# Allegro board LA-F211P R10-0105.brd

Outline 172.74 x 113.1 mm; copper layers: TOP, GND1, IN1, GND2, IN2, VCC, GND3, IN3, GND4, BOTTOM. Coordinates in mm from the lower left corner of the outline.
Outline path: 0,71.25 0,57.53 arc(0.09,57.24) 0.33,57.06 arc(0.57,56.88) 0.66,56.59 0.66,54.99 arc(0.7,54.8) 0.81,54.63 2.16,53.28 arc(2.27,53.11) 2.31,52.92 2.31,49.34 arc(2.27,49.15) 2.16,48.98 1.76,48.58 arc(1.65,48.41) 1.61,48.22 1.61,47.2 arc(1.5,46.88) 1.2,46.71 arc(0.91,46.54) 0.8,46.22 0.8,28.6 arc(0.95,28.24) 1.31,28.1 arc(1.66,27.96) 1.81,27.6 1.81,21.51 arc(1.66,21.16) 1.31,21.01 1.16,21.01 arc(0.81,20.86) 0.66,20.51 0.66,2.97 arc(0.81,2.62) 1.16,2.47 1.31,2.47 arc(1.66,2.32) 1.81,1.97 1.81,1 arc(2.1,0.29) 2.81,0 97.06,0 97.06,0.32 arc(98.21,1.47) 99.36,0.32 99.36,0 108.01,0 arc(108.72,0.29) 109.01,1 109.01,2.2 arc(109.16,2.55) 109.51,2.7 115.51,2.7 arc(115.81,2.6) 115.99,2.35 arc(116.17,2.1) 116.46,2 133.66,2 arc(134.01,1.85) 134.16,1.5 134.16,0.5 arc(134.31,0.15) 134.66,0 154.16,0 arc(154.51,0.15) 154.66,0.5 arc(154.81,0.85) 155.16,1 160.16,1 arc(160.51,0.85) 160.66,0.5 arc(160.81,0.15) 161.16,0 170.74,0 arc(172.15,0.59) 172.74,2 172.74,7 arc(172.52,7.92) 171.9,8.63 arc(161.15,19.71) 155.07,33.9 arc(154.79,34.35) 154.29,34.52 153.55,34.52 arc(153.04,34.7) 152.76,35.17 arc(152.24,38.83) 152.03,42.51 arc(152.26,43.08) 152.83,43.32 153.22,43.32 arc(153.79,43.55) 154.02,44.12 154.02,93.99 arc(153.89,94.49) 153.52,94.85 arc(152.79,95.59) 152.52,96.59 152.52,108.3 arc(152.67,108.65) 153.02,108.8 153.42,108.8 arc(153.77,108.95) 153.92,109.3 153.92,112.1 arc(153.63,112.81) 152.92,113.1 149.94,113.1 arc(149.66,113.06) 149.41,112.95 arc(148.9,112.73) 148.36,112.65 76.23,112.65 arc(75.52,112.36) 75.23,111.65 75.23,109.65 arc(74.94,108.94) 74.23,108.65 29.23,108.65 arc(27.82,108.06) 27.23,106.65 27.23,105.73 arc(26.64,104.32) 25.23,103.73 17.61,103.73 arc(16.2,104.32) 15.61,105.73 15.61,108.65 arc(15.02,110.06) 13.61,110.65 9.07,110.65 arc(8.49,110.71) 7.92,110.88 arc(7.55,110.99) 7.16,111.03 2.66,111.03 arc(1.25,110.44) 0.66,109.03 0.66,108.72 arc(0.81,108.37) 1.16,108.22 3.56,108.22 arc(4.46,107.32) 3.56,106.42 2.35,106.42 arc(1.64,106.13) 1.35,105.42 1.35,103.69 arc(1.5,103.34) 1.85,103.19 5.25,103.19 arc(5.75,103.69) 6.25,103.19 6.25,94.24 arc(5.75,93.74) 5.25,94.24 1.16,94.24 arc(0.81,94.09) 0.66,93.74 0.66,93.08 arc(0.77,92.77) 1.04,92.59 arc(1.6,92.24) 1.81,91.62 1.81,89.62 arc(1.6,89) 1.04,88.65 arc(0.77,88.47) 0.66,88.16 0.66,87.49 arc(0.81,87.14) 1.16,86.99 5.25,86.99 arc(5.75,87.49) 6.25,86.99 6.25,78.04 arc(5.75,77.54) 5.25,78.04 1.85,78.04 arc(1.5,77.89) 1.35,77.54 1.35,75.91 arc(1.5,75.56) 1.85,75.41 3.56,75.41 arc(4.2,75.15) 4.46,74.51 4.46,74.01 arc(4.2,73.37) 3.56,73.11 1.16,73.11 arc(0.81,72.96) 0.66,72.61 0.66,72.19 arc(0.57,71.9) 0.33,71.72 arc(0.09,71.54) 0,71.25

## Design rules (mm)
constraint set DEFAULT: min track width 0.127
net group ACC2_I2C_SCK: nets ACC2_I2C_SCK ACC2_I2C_SDA
net group ACC2_I2C_SCK1: nets ACC2_I2C_SCK1 ACC2_I2C_SDA1
net group CLK_PCIE_0: nets CLK_PCIE_N0 CLK_PCIE_P0
net group CLK_PEG_7: nets CLK_PEG_N7 CLK_PEG_P7
net group CPU_DP1_0: nets CPU_DP1_N0 CPU_DP1_P0
net group CPU_DP1_1: nets CPU_DP1_N1 CPU_DP1_P1
net group CPU_DP1_2: nets CPU_DP1_N2 CPU_DP1_P2
net group CPU_DP1_3: nets CPU_DP1_N3 CPU_DP1_P3
net group CPU_DP1_AUX: nets CPU_DP1_AUXN CPU_DP1_AUXP
net group CPU_DP2_0: nets CPU_DP2_N0 CPU_DP2_P0
net group CPU_DP2_0_C: nets CPU_DP2_N0_C CPU_DP2_P0_C
net group CPU_DP2_1: nets CPU_DP2_N1 CPU_DP2_P1
net group CPU_DP2_1_C: nets CPU_DP2_N1_C CPU_DP2_P1_C
net group CPU_DP2_2: nets CPU_DP2_N2 CPU_DP2_P2
net group CPU_DP2_2_C: nets CPU_DP2_N2_C CPU_DP2_P2_C
net group CPU_DP2_3: nets CPU_DP2_N3 CPU_DP2_P3
net group CPU_DP2_3_C: nets CPU_DP2_N3_C CPU_DP2_P3_C
net group CPU_DP2_AUX: nets CPU_DP2_AUXN CPU_DP2_AUXP
net group CPU_DP2_AUX_C: nets CPU_DP2_AUXN_C CPU_DP2_AUXP_C
net group CPU_DP3_AUX: nets CPU_DP3_AUXN CPU_DP3_AUXP
net group CPU_DP3_AUX_C: nets CPU_DP3_AUXN_C CPU_DP3_AUXP_C
net group CRITICAL: nets CLINK_CLK SUSCLK
net group DDR-ALERT: nets DDR_A_ALERT# DDR_B_ALERT#
net group GPU_I2C_SCL_R: nets GPU_I2C_SCL_R GPU_I2C_SDA_R
net group HDA_CLK: nets HDA_BIT_CLK HDA_BIT_CLK_R
net group I2C0_SCK_TS: nets I2C0_SCK_TS I2C0_SDA_TS
net group ISH_I2C0_SCK: nets ISH_I2C0_SCK ISH_I2C0_SDA
net group PBAT_CHARGER_SMBCLK: nets PBAT_CHARGER_SMBCLK PBAT_CHARGER_SMBDAT
net group PCH_CPU_BCLK: nets PCH_CPU_BCLK_N PCH_CPU_BCLK_P
net group PCH_CPU_PCIBCLK: nets PCH_CPU_PCIBCLK_N PCH_CPU_PCIBCLK_P
net group PCIE_PRX_C_DTX_5: nets PCIE_PRX_C_DTX_N5 PCIE_PRX_C_DTX_P5
net group PCIE_PRX_C_TTX_9: nets PCIE_PRX_C_TTX_N9 PCIE_PRX_C_TTX_P9
net group PCIE_PRX_C_TTX_10: nets PCIE_PRX_C_TTX_N10 PCIE_PRX_C_TTX_P10
net group PCIE_PRX_C_TTX_11: nets PCIE_PRX_C_TTX_N11 PCIE_PRX_C_TTX_P11
net group PCIE_PRX_C_TTX_12: nets PCIE_PRX_C_TTX_N12 PCIE_PRX_C_TTX_P12
net group PCIE_PRX_DTX_1: nets PCIE_PRX_DTX_N1 PCIE_PRX_DTX_P1
net group PCIE_PRX_DTX_5: nets PCIE_PRX_DTX_N5 PCIE_PRX_DTX_P5
net group PCIE_PRX_DTX_14: nets PCIE_PRX_DTX_N14 PCIE_PRX_DTX_P14
net group PCIE_PRX_DTX_15: nets PCIE_PRX_DTX_N15 PCIE_PRX_DTX_P15
net group PCIE_PRX_DTX_16: nets PCIE_PRX_DTX_N16 PCIE_PRX_DTX_P16
net group PCIE_PRX_TTX_9: nets PCIE_PRX_TTX_N9 PCIE_PRX_TTX_P9
net group PCIE_PRX_TTX_10: nets PCIE_PRX_TTX_N10 PCIE_PRX_TTX_P10
net group PCIE_PRX_TTX_11: nets PCIE_PRX_TTX_N11 PCIE_PRX_TTX_P11
net group PCIE_PRX_TTX_12: nets PCIE_PRX_TTX_N12 PCIE_PRX_TTX_P12
net group PCIE_PTX_C_DRX_5: nets PCIE_PTX_C_DRX_N5 PCIE_PTX_C_DRX_P5
net group PCIE_PTX_C_DRX_14: nets PCIE_PTX_C_DRX_N14 PCIE_PTX_C_DRX_P14
net group PCIE_PTX_C_DRX_15: nets PCIE_PTX_C_DRX_N15 PCIE_PTX_C_DRX_P15
net group PCIE_PTX_C_DRX_16: nets PCIE_PTX_C_DRX_N16 PCIE_PTX_C_DRX_P16
net group PCIE_PTX_C_RD_DRX_1: nets PCIE_PTX_C_RD_DRX_N1 PCIE_PTX_C_RD_DRX_P1
net group PCIE_PTX_C_TRX_9: nets PCIE_PTX_C_TRX_N9 PCIE_PTX_C_TRX_P9
net group PCIE_PTX_C_TRX_10: nets PCIE_PTX_C_TRX_N10 PCIE_PTX_C_TRX_P10
net group PCIE_PTX_C_TRX_11: nets PCIE_PTX_C_TRX_N11 PCIE_PTX_C_TRX_P11
net group PCIE_PTX_C_TRX_12: nets PCIE_PTX_C_TRX_N12 PCIE_PTX_C_TRX_P12
net group PCIE_PTX_DRX_1: nets PCIE_PTX_DRX_N1 PCIE_PTX_DRX_P1
net group PCIE_PTX_DRX_5: nets PCIE_PTX_DRX_N5 PCIE_PTX_DRX_P5
net group PCIE_PTX_DRX_14: nets PCIE_PTX_DRX_N14 PCIE_PTX_DRX_P14
net group PCIE_PTX_DRX_15: nets PCIE_PTX_DRX_N15 PCIE_PTX_DRX_P15
net group PCIE_PTX_DRX_16: nets PCIE_PTX_DRX_N16 PCIE_PTX_DRX_P16
net group PCIE_PTX_TRX_9: nets PCIE_PTX_TRX_N9 PCIE_PTX_TRX_P9
net group PCIE_PTX_TRX_10: nets PCIE_PTX_TRX_N10 PCIE_PTX_TRX_P10
net group PCIE_PTX_TRX_11: nets PCIE_PTX_TRX_N11 PCIE_PTX_TRX_P11
net group PCIE_PTX_TRX_12: nets PCIE_PTX_TRX_N12 PCIE_PTX_TRX_P12
net group PD_USB20_P2: nets PD_USB20_N2 PD_USB20_P2
net group PECI: nets PCH_PCIE_WAKE# PCIE_WAKE#
net group REM_DIODE1: nets REM_DIODE1_N REM_DIODE1_P
net group REM_DIODE2: nets REM_DIODE2_N REM_DIODE2_P
net group REM_DIODE3: nets REM_DIODE3_N REM_DIODE3_P
net group REM_DIODE4: nets REM_DIODE4_N REM_DIODE4_P
net group SD_CLK: nets SD_CLK SD_CLK_R
net group SMB: nets SMBCLK SMBDAT
net group SML1_SMBCLK: nets SML1_SMBCLK SML1_SMBDAT
net group SPI_CLK: nets PCH_SPI_CLK PCH_SPI_CLK_0_R
net group TBT_A_AUX_C: nets TBT_A_AUX_N_C TBT_A_AUX_P_C
net group TBT_B_AUX_C: nets TBT_B_AUX_N_C TBT_B_AUX_P_C
net group TBTA_DPSRC_AUX: nets TBTA_DPSRC_AUX_N TBTA_DPSRC_AUX_P
net group TBTA_DPSRC_AUX_R: nets TBTA_DPSRC_AUX_N_R TBTA_DPSRC_AUX_P_R
net group TBTA_USB2_D_P: nets TBTA_USB2_D_N TBTA_USB2_D_P
net group TBTB_DPSRC_AUX: nets TBTB_DPSRC_AUX_N TBTB_DPSRC_AUX_P
net group TBTB_DPSRC_AUX_R: nets TBTB_DPSRC_AUX_N_R TBTB_DPSRC_AUX_P_R
net group TBTB_USB2_D_P: nets TBTB_USB2_D_N TBTB_USB2_D_P
net group THERMTRIP: nets H_THERMTRIP# H_THERMTRIP#_R
net group USB3_PRX_MTX_2: nets USB3_PRX_MTX_N2 USB3_PRX_MTX_P2
net group USB20_2: nets USB20_N2 USB20_P2
net group VCCGT_SENSE: nets VCCGT_SENSE VSSGT_SENSE
net group VSS_SENSE: nets VCC_SENSE VSS_SENSE
net group VSSIO_SENSE: nets VCCIO_SENSE VSSIO_SENSE
net group VSSSA_SENSE: nets VCCSA_SENSE VSSSA_SENSE
net group 20: nets SD_LN0_M SD_LN0_P SD_LN1_M SD_LN1_P
net group 85H-AR: nets TBT_A_TRX_DTX_N1 TBT_A_TRX_DTX_N2 TBT_A_TRX_DTX_P1 TBT_A_TRX_DTX_P2 TBT_A_TTX_C_DRX_N1 TBT_A_TTX_C_DRX_N2 TBT_A_TTX_C_DRX_P1 TBT_A_TTX_C_DRX_P2 TBT_A_TTX_DRX_N1 TBT_A_TTX_DRX_N2 TBT_A_TTX_DRX_P1 TBT_A_TTX_DRX_P2 TBT_B_TRX_DTX_N1 TBT_B_TRX_DTX_N2 TBT_B_TRX_DTX_P1 TBT_B_TRX_DTX_P2 TBT_B_TTX_C_DRX_N1 TBT_B_TTX_C_DRX_N2 TBT_B_TTX_C_DRX_P1 TBT_B_TTX_C_DRX_P2 TBT_B_TTX_DRX_N1 TBT_B_TTX_DRX_N2 TBT_B_TTX_DRX_P1 TBT_B_TTX_DRX_P2
net group ASYNCHRONOUS: nets CPU_TRIGGER CPU_TRIGGER_R H_CATERR# H_CPUPWRGD H_PM_DOWN H_PM_DOWN_R H_PM_SYNC_R H_PROCHOT# H_PROCHOT#_R H_PROCHOT#_R1 H_VCCST_PWRGD_P N121388945 PCH_TRIGGER PCH_TRIGGER_R PLTRST_CPU#
net group DDI-DP3: nets CPU_DP3_N0 CPU_DP3_N0_C CPU_DP3_N1 CPU_DP3_N1_C CPU_DP3_N2 CPU_DP3_N2_C CPU_DP3_N3 CPU_DP3_N3_C CPU_DP3_P0 CPU_DP3_P0_C CPU_DP3_P1 CPU_DP3_P1_C CPU_DP3_P2 CPU_DP3_P2_C CPU_DP3_P3 CPU_DP3_P3_C
net group DDRA-D0: nets DDR_A_D0 DDR_A_D1 DDR_A_D2 DDR_A_D3 DDR_A_D4 DDR_A_D5 DDR_A_D6 DDR_A_D7
net group DDRA-D1: nets DDR_A_D8 DDR_A_D9 DDR_A_D10 DDR_A_D11 DDR_A_D12 DDR_A_D13 DDR_A_D14 DDR_A_D15
net group DDRA-D2: nets DDR_A_D16 DDR_A_D17 DDR_A_D18 DDR_A_D19 DDR_A_D20 DDR_A_D21 DDR_A_D22 DDR_A_D23
net group DDRA-D3: nets DDR_A_D24 DDR_A_D25 DDR_A_D26 DDR_A_D27 DDR_A_D28 DDR_A_D29 DDR_A_D30 DDR_A_D31
net group DDRA-D4: nets DDR_A_D32 DDR_A_D33 DDR_A_D34 DDR_A_D35 DDR_A_D36 DDR_A_D37 DDR_A_D38 DDR_A_D39
net group DDRA-D5: nets DDR_A_D40 DDR_A_D41 DDR_A_D42 DDR_A_D43 DDR_A_D44 DDR_A_D45 DDR_A_D46 DDR_A_D47
net group DDRA-D6: nets DDR_A_D48 DDR_A_D49 DDR_A_D50 DDR_A_D51 DDR_A_D52 DDR_A_D53 DDR_A_D54 DDR_A_D55
net group DDRA-D7: nets DDR_A_D56 DDR_A_D57 DDR_A_D58 DDR_A_D59 DDR_A_D60 DDR_A_D61 DDR_A_D62 DDR_A_D63
net group DDRB-D0: nets DDR_B_D0 DDR_B_D1 DDR_B_D2 DDR_B_D3 DDR_B_D4 DDR_B_D5 DDR_B_D6 DDR_B_D7
net group DDRB-D1: nets DDR_B_D8 DDR_B_D9 DDR_B_D10 DDR_B_D11 DDR_B_D12 DDR_B_D13 DDR_B_D14 DDR_B_D15
net group DDRB-D2: nets DDR_B_D16 DDR_B_D17 DDR_B_D18 DDR_B_D19 DDR_B_D20 DDR_B_D21 DDR_B_D22 DDR_B_D23
net group DDRB-D3: nets DDR_B_D24 DDR_B_D25 DDR_B_D26 DDR_B_D27 DDR_B_D28 DDR_B_D29 DDR_B_D30 DDR_B_D31
net group DDRB-D4: nets DDR_B_D32 DDR_B_D33 DDR_B_D34 DDR_B_D35 DDR_B_D36 DDR_B_D37 DDR_B_D38 DDR_B_D39
net group DDRB-D5: nets DDR_B_D40 DDR_B_D41 DDR_B_D42 DDR_B_D43 DDR_B_D44 DDR_B_D45 DDR_B_D46 DDR_B_D47
net group DDRB-D6: nets DDR_B_D48 DDR_B_D49 DDR_B_D50 DDR_B_D51 DDR_B_D52 DDR_B_D53 DDR_B_D54 DDR_B_D55
net group DDRB-D7: nets DDR_B_D56 DDR_B_D57 DDR_B_D58 DDR_B_D59 DDR_B_D60 DDR_B_D61 DDR_B_D62 DDR_B_D63
net group DDRC-6(7: nets DDR_A_CKE0 DDR_A_CS#0 DDR_A_ODT0 DDR_B_CKE0 DDR_B_CS#0 DDR_B_ODT0
net group DDRCLK-16/16: nets DDR_A_CLK0 DDR_A_CLK#0 DDR_B_CLK0 DDR_B_CLK#0
net group DDRDQS-16/25: nets DDR_A_DQS0 DDR_A_DQS1 DDR_A_DQS2 DDR_A_DQS3 DDR_A_DQS4 DDR_A_DQS5 DDR_A_DQS6 DDR_A_DQS7 DDR_A_DQS#0 DDR_A_DQS#1 DDR_A_DQS#2 DDR_A_DQS#3 DDR_A_DQS#4 DDR_A_DQS#5 DDR_A_DQS#6 DDR_A_DQS#7 DDR_B_DQS0 DDR_B_DQS1 DDR_B_DQS2 DDR_B_DQS3 DDR_B_DQS4 DDR_B_DQS5 DDR_B_DQS6 DDR_B_DQS7 DDR_B_DQS#0 DDR_B_DQS#1 DDR_B_DQS#2 DDR_B_DQS#3 DDR_B_DQS#4 DDR_B_DQS#5 DDR_B_DQS#6 DDR_B_DQS#7
net group DDRMA-6(7: nets DDR_A_ACT# DDR_A_BA0 DDR_A_BA1 DDR_A_BG0 DDR_A_BG1 DDR_A_MA0 DDR_A_MA1 DDR_A_MA2 DDR_A_MA3 DDR_A_MA4 DDR_A_MA5 DDR_A_MA6 DDR_A_MA7 DDR_A_MA8 DDR_A_MA9 DDR_A_MA10 DDR_A_MA11 DDR_A_MA12 DDR_A_MA13 DDR_A_MA14 DDR_A_MA15 DDR_A_MA16 DDR_A_PARITY DDR_B_ACT# DDR_B_BA0 DDR_B_BA1 DDR_B_BG0 DDR_B_BG1 DDR_B_MA0 DDR_B_MA1 DDR_B_MA2 DDR_B_MA3 DDR_B_MA4 DDR_B_MA5 DDR_B_MA6 DDR_B_MA7 DDR_B_MA8 DDR_B_MA9 DDR_B_MA10 DDR_B_MA11 DDR_B_MA12 DDR_B_MA13 DDR_B_MA14 DDR_B_MA15 DDR_B_MA16 DDR_B_PARITY
net group DMI: nets DMI_CRX_PTX_N0 DMI_CRX_PTX_N1 DMI_CRX_PTX_N2 DMI_CRX_PTX_N3 DMI_CRX_PTX_P0 DMI_CRX_PTX_P1 DMI_CRX_PTX_P2 DMI_CRX_PTX_P3 DMI_CTX_PRX_N0 DMI_CTX_PRX_N1 DMI_CTX_PRX_N2 DMI_CTX_PRX_N3 DMI_CTX_PRX_P0 DMI_CTX_PRX_P1 DMI_CTX_PRX_P2 DMI_CTX_PRX_P3
net group EDP_12_15: nets EDP_AUXN EDP_AUXN_C EDP_AUXN_R EDP_AUXP EDP_AUXP_C EDP_AUXP_R EDP_TXN0 EDP_TXN0_C EDP_TXN0_R EDP_TXN1 EDP_TXN1_C EDP_TXN1_R EDP_TXN2 EDP_TXN2_C EDP_TXN2_R EDP_TXN3 EDP_TXN3_C EDP_TXN3_R EDP_TXP0 EDP_TXP0_C EDP_TXP0_R EDP_TXP1 EDP_TXP1_C EDP_TXP1_R EDP_TXP2 EDP_TXP2_C EDP_TXP2_R EDP_TXP3 EDP_TXP3_C EDP_TXP3_R
net group HDA: nets HDA_RST# HDA_SDIN0 HDA_SDOUT HDA_SDOUT_R HDA_SYNC HDA_SYNC_R
net group I2C: nets DB_SEN_I2C_SCK DB_SEN_I2C_SDA ISH_I2C0_SCK_R ISH_I2C0_SDA_R
net group PLATFORM-CLK: nets CLK_PCIE_N3 CLK_PCIE_N6 CLK_PCIE_N8 CLK_PCIE_P3 CLK_PCIE_P6 CLK_PCIE_P8 CPU_24MHZ_N CPU_24MHZ_P
net group PWR_GND: nets +0.6V_A_VREFDQ +0.6V_B_VREFDQ +0.6V_DDR_B_VREFDQ +0.6V_DDR_VREFCA +0.6V_VREFCA +0.6VS +0.6VSP +0.95VSP +1.2V_DDRP +1.2V_VCCPLL_OC +1.8V_3.3V_ALW_VTR3 +1.8VALWP +1V_MPHY_MPHYPLL +1V_PCH +1V_PCH_AZPLL +1V_PCH_CLK5 +1V_PCH_USBPLL +1V_VCCDSW +1VALWP +3.3V_1.8V_ESPI +3.3V_1.8V_PGPPA +3.3V_EC5105 +3.3V_EC_PLL +3.3VDX_SSD +3V_LDO +3V_LDOP +3V_PCH_AZIO +3V_PCH_DSW +3V_PCH_SPI +3V_ROM +3V_TBT +3V_TBT_S0 +3VA_TBT +3VA_TBT_LC +3VALWP +3VD_LDO +3VDP +3VLP +3VS_CAM +3VS_CR +3VS_FP +3VS_SENSOR +3VS_TPM +3VS_TPM_VSB +3VS_TS +5V_VBUS1 +5V_VBUS2 +5VALW_LDO +5VALWP +5VD +5VD_LDO +5VDP +5VS +CCG_VBUS1 +CCG_VBUS2 +CHG_SRC_20V +DCPRTC +EC_DEBUG_VCC +INV_PWR_SRC +LCDVDD +ODR_PWR +PECI_VREF +RTC_CELL_VBAT +RTCBATT +RTCVCC +SD_VDD2 +TBT_VBUS1 +TBT_VBUS2 +TPM_VDD +VBATT +VCC0V9_CIO +VCC0V9_DP +VCC0V9_PCIE +VCC0V9_USB +VCCST +VCCSTG +VDD08 +VDD08P +VDD_33 +VDDCI +VGA_CORE_LX1 +VGA_CORE_LX2 +VGA_CORE_LX3 +VGA_CORE_LX4 +VPP_25 +VR_CAP +VSS_PLL
net group RTC: nets PCH_RTCRST# PCH_RTCX1 PCH_RTCX2 PCH_SRTCRST#
net group SATA: nets SATA_PRX_DTX_N0B SATA_PRX_DTX_P0B SATA_PTX_C_DRX_N0B SATA_PTX_C_DRX_P0B SATA_PTX_DRX_N0B SATA_PTX_DRX_P0B
net group SD: nets SD_CD# SD_CMD SD_CMD_R SD_D2 SD_D2_R SD_D3 SD_D3_R SD_RCLK_M SD_RCLK_M_R SD_RCLK_P SD_RCLK_P_R SD_REG2
net group SPI: nets PCH_SPI_CS#0 PCH_SPI_HOLD# PCH_SPI_SI PCH_SPI_SI_0_R PCH_SPI_SO PCH_SPI_SO_0_R PCH_SPI_WP# PCH_SPI_WP#_0_R
net group SVID: nets VR_SVID_ALERT# VR_SVID_ALERT#_R VR_SVID_CLK VR_SVID_DATA
net group USB2.0: nets PD_USB20_N1 PD_USB20_N1_B PD_USB20_N1_B_R PD_USB20_N1_T PD_USB20_N1_T_R PD_USB20_N2_B PD_USB20_N2_B_R PD_USB20_N2_T PD_USB20_N2_T_R PD_USB20_P1 PD_USB20_P1_B PD_USB20_P1_B_R PD_USB20_P1_T PD_USB20_P1_T_R PD_USB20_P2_B PD_USB20_P2_B_R PD_USB20_P2_T PD_USB20_P2_T_R USB20_N1 USB20_N1_R USB20_N3 USB20_N4 USB20_N6 USB20_N8 USB20_N10 USB20_N10_FP USB20_N11 USB20_P1 USB20_P1_R USB20_P3 USB20_P4 USB20_P6 USB20_P8 USB20_P10 USB20_P10_FP USB20_P11
net group USB3.0: nets USB3_PRX_MTX_N1 USB3_PRX_MTX_P1 USB3_PTX_MRX_N1 USB3_PTX_MRX_N2 USB3_PTX_MRX_P1 USB3_PTX_MRX_P2 USB3RN4 USB3RP4 USB3TN4 USB3TP4
nets with their own width: min track width 0.152; nets CCG5_VBUS1_CSN_P1 CCG5_VBUS2_CSN_P2
nets with their own width: min track width 0.203; nets N133320954
nets with their own width: min track width 0.254; nets N133318479 N133363191 N150412421 PCIE_RCOMPN PCIE_RCOMPP
nets with their own width: min track width 0.381; nets TBT_A_CC1 TBT_A_CC2 TBT_B_CC1 TBT_B_CC2
nets with their own width: min track width 0.508; nets +1.2V_DDR +1.05_VMM_ALW +1.05_VMMP_ALW +1.8VALW +1V_MPHY +1V_PCH_PRIM +1VALW +2.5V_MEM +3V_PCH +3VALW +3VALW_DSW_R +3VD +3VS +5VALW +CHG_VIN_20V +DC_IN_1 +DC_IN_2 +EVDDC +EVDDQ +RTCVCC_R +VBUS1_DC_SS +VBUS2_DC_SS +VCC_CORE +VCCGT +VCCIO +VCCSA +VDD12 +VDD_18 +VDD_33_GPU +VDDAN_18 +VDDCIP +VDDIO_18 +VDP_ZVDD_08 +VREFEXTA +VSYS B+ GND
nets with their own width: min track width 1.524; nets B+_CAM

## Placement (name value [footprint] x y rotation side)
BAT100  DEREN_40-42507-01001RHF  [DEREN_40-42507-01001RHF_10P-T]  131.28 19.33 180 bottom
C2  22P_0402_50V8J  [C_0402]  66.21 25.06 90 top
C3  1U_0402_6.3V6K~D  [C_0402]  71.95 22.68 90 top
C4  0.1U_0402_25V6K~D  [C_0402]  66.27 21.38 270 top
C93  1U_0402_6.3V6K~D  [C_0402]  65.12 85.98 90 top
C96  0.1U_0402_10V7K  [C_0402]  64.74 90.26 270 top
C97  4700P_0402_25V7K  [C_0402]  66.9 89.35 90 top
C99  1000P_0402_50V7K~D  [C_0402]  67.79 89.35 90 top
C101  1U_0402_6.3V6K~D  [C_0402]  69.5 85.86 90 top
C103  0.1U_0402_10V7K  [C_0402]  69.95 90.84 270 top
C185  0.1U_0201_10V6K  [C_0201]  66.65 15.04 270 bottom
C186  0.1U_0201_10V6K  [C_0201]  66.01 15.04 270 bottom
C190  2.2U_0603_25V6K  [C_0603]  163.28 1.77 90 bottom
C191  0.1U_0402_10V7K  [C_0402]  161.68 4.1 0 bottom
C225  0.1U_0201_10V6K  [C_0201]  68.87 16.19 270 bottom
C375  0.1U_0402_25V6K~D  [C_0402]  16.05 5.66 180 top
C376  0.1U_0402_25V6K~D  [C_0402]  15.96 3.69 270 top
C377  0.1U_0402_25V6K~D  [C_0402]  16.07 6.58 180 top
C1068  10U_0603_25V6M  [C_0603]  147.61 109.68 90 top
C1083  100P_0201_50V8J  [C_0201]  40.61 87.93 90 bottom
C1089  39P_0201_50V8J  [C_0201]  39.84 80.56 0 top
C1090  100P_0201_50V8J  [C_0201]  39.84 81.15 0 top
C1091  39P_0201_50V8J  [C_0201]  34.71 84.4 180 top
C1092  100P_0201_50V8J  [C_0201]  34.71 83.76 180 top
C1093  39P_0201_50V8J  [C_0201]  39.79 83.84 0 top
C1094  100P_0201_50V8J  [C_0201]  39.79 84.42 0 top
C1095  39P_0201_50V8J  [C_0201]  33.25 86.44 90 top
C1096  100P_0201_50V8J  [C_0201]  35.91 83.14 180 top
C1097  39P_0201_50V8J  [C_0201]  37.86 84.4 0 top
C1098  100P_0201_50V8J  [C_0201]  37.21 83.81 90 top
C1099  39P_0201_50V8J  [C_0201]  38.52 77.97 0 top
C1100  100P_0201_50V8J  [C_0201]  37.87 77.96 270 top
C1101  39P_0201_50V8J  [C_0201]  34.6 81.22 180 top
C1102  100P_0201_50V8J  [C_0201]  35.26 81.86 0 top
C1103  39P_0201_50V8J  [C_0201]  39.15 79.27 270 top
C1104  100P_0201_50V8J  [C_0201]  40.31 79.27 270 top
C1105  39P_0201_50V8J  [C_0201]  35.25 78.62 270 top
C1106  100P_0201_50V8J  [C_0201]  35.9 78.62 270 top
C1107  39P_0201_50V8J  [C_0201]  39.15 81.22 180 top
C1108  100P_0201_50V8J  [C_0201]  39.15 83.15 180 top
C1109  39P_0201_50V8J  [C_0201]  37.19 78.68 180 top
C1110  100P_0201_50V8J  [C_0201]  37.19 79.27 180 top
C1111  39P_0201_50V8J  [C_0201]  36 79.34 180 top
C1112  100P_0201_50V8J  [C_0201]  36.01 79.94 90 top
C1115  39P_0201_50V8J  [C_0201]  34.71 87.93 90 bottom
C1116  100P_0201_50V8J  [C_0201]  34.71 89.2 90 bottom
C2984  0.1U_0201_10V6K  [C_0201]  147.16 98.77 90 top
C3002  0.1U_0201_10V6K  [C_0201]  16.38 74.4 180 top
C3003  0.1U_0201_10V6K  [C_0201]  55.37 97.11 0 top
C3004  0.1U_0201_10V6K  [C_0201]  55.37 96.54 0 top
C3005  10U_0402_6.3V6M  [C_0402]  55.39 97.87 0 top
C3007  220P_0402_50V7K  [C_0402]  18.45 32.23 270 top
C3021  0.1U_0402_25V6K~D  [C_0402]  38.58 6.55 90 top
C3022  10U_0402_6.3V6M  [C_0402]  53.35 70.35 270 bottom
C3023  10U_0402_6.3V6M  [C_0402]  60.18 72.21 180 bottom
C3024  1U_0201_6.3V6M  [C_0201]  53.5 72.32 270 bottom
C3310  0.1U_0201_10V6K  [C_0201]  15.08 29.08 270 top
C3311  2200P_0402_25V7K  [C_0402]  155.88 19.75 180 top
C3312  2.2U_0603_25V6K  [C_0603]  156.22 24.78 114.7 top
C3313  0.1U_0402_10V7K  [C_0402]  68.74 84.55 270 top
C3314  1U_0402_25V6K  [C_0402]  141.19 83.75 0 top
C3315  0.1U_0201_25V6K  [C_0201]  142.08 89.06 90 top
CC139  0.1U_0201_10V6K  [C_0201]  25.79 40.85 180 top
CC170  0.1U_0201_10V6K  [C_0201]  27.06 47.45 180 top
CC171  1U_0402_6.3V6K  [C_0402]  14.96 31.08 270 top
CD58  4.7U_0402_6.3V6M  [C_0402]  86.08 23.88 90 bottom
CD59  0.22U_0402_10V6K  [C_0402]  93.32 15.53 270 top
CD60  .1U_0402_16V7K  [C_0402]  87.92 23.88 90 bottom
CD61  0.01U_0402_16V7K  [C_0402]  87.68 9.61 180 bottom
CD62  47P_0402_50V8J  [C_0402]  87.86 8.41 270 bottom
CD63  15P_0402_50V8J  [C_0402]  87.03 23.88 90 bottom
CD64  0.22U_0402_10V6K  [C_0402]  92.05 12.99 270 top
CD65  0.22U_0402_10V6K  [C_0402]  92.94 12.99 270 top
CD66  0.22U_0402_10V6K  [C_0402]  94.21 15.53 270 top
CD67  0.22U_0402_10V6K  [C_0402]  95.35 16.67 270 top
CD68  0.22U_0402_10V6K  [C_0402]  96.24 16.67 270 top
CD69  0.22U_0402_10V6K  [C_0402]  95.35 19.84 270 top
CD70  0.22U_0402_10V6K  [C_0402]  96.24 19.84 270 top
CD111  0.1U_0402_10V6K  [C_0402]  141.65 110 180 top
CD112  0.1U_0402_10V6K  [C_0402]  114.84 107.22 270 top
CD113  0.1U_0402_10V6K  [C_0402]  119.02 106.38 0 bottom
CD114  0.1U_0201_10V6K  [C_0201]  93.95 106.64 90 bottom
CD256  10U_0402_6.3V6M  [C_0402]  118.73 107.92 90 bottom
CD263  0.047U_0201_10V6K  [C_0201]  130.29 106.57 270 bottom
CD264  0.047U_0402_10V7K  [C_0402]  130.29 105.73 90 top
CD265  1U_0201_6.3V6M  [C_0201]  139.81 110.38 180 top
CD266  1U_0201_6.3V6M  [C_0201]  140.67 99.84 0 top
CD267  1U_0201_6.3V6M  [C_0201]  140.75 96.74 270 top
CD268  1U_0201_6.3V6M  [C_0201]  130.27 97.26 90 top
CD269  1U_0201_6.3V6M  [C_0201]  130.29 96.63 270 top
CD270  1U_0201_6.3V6M  [C_0201]  130.3 101.99 90 top
CD271  1U_0201_6.3V6M  [C_0201]  119.8 105.45 90 top
CD272  1U_0201_6.3V6M  [C_0201]  119.8 101.16 90 top
CD273  10U_0402_6.3V6M  [C_0402]  127.39 93.94 0 top
CD274  1U_0201_6.3V6M  [C_0201]  119.81 95.74 270 top
CD275  10U_0402_6.3V6M  [C_0402]  120.58 93.94 180 top
CD276  10U_0402_6.3V6M  [C_0402]  139.52 93.94 0 top
CD277  10U_0402_6.3V6M  [C_0402]  134.69 93.94 0 top
CD278  10U_0402_6.3V6M  [C_0402]  122.56 93.94 0 top
CD279  1U_0201_6.3V6M  [C_0201]  130.27 107.96 270 top
CD280  1U_0201_6.3V6M  [C_0201]  130.27 108.58 90 top
CD281  10U_0402_6.3V6M  [C_0402]  140.8 97.62 0 top
CD282  1U_0201_6.3V6M  [C_0201]  119.8 108.08 90 top
CD283  1U_0201_6.3V6M  [C_0201]  119.8 107.22 270 top
CD284  10U_0402_6.3V6M  [C_0402]  118.72 108.07 90 top
CD285  1U_0201_6.3V6M  [C_0201]  142.49 108.22 90 top
CD286  1U_0201_6.3V6M  [C_0201]  143.42 107.7 90 top
CD287  10U_0402_6.3V6M  [C_0402]  141.49 102.76 270 top
CD288  1U_0201_6.3V6M  [C_0201]  142.53 102.52 270 top
CD289  1U_0201_6.3V6M  [C_0201]  143.42 102.52 270 top
CD290  10U_0402_6.3V6M  [C_0402]  141.73 108.1 90 top
CD291  0.022U_0402_16V7K~D  [C_0402]  139.9 89.83 180 top
CD292  0.047U_0402_10V7K  [C_0402]  140.65 105.49 270 top
CD293  1U_0201_6.3V6M  [C_0201]  130.28 107.77 270 bottom
CD295  10U_0402_6.3V6M  [C_0402]  139.51 93.93 0 bottom
CD296  1U_0201_6.3V6M  [C_0201]  129.84 110.45 180 bottom
CD297  10U_0402_6.3V6M  [C_0402]  144.08 110.31 90 bottom
CD298  10U_0402_6.3V6M  [C_0402]  125.41 93.94 180 top
CD299  1U_0201_6.3V6M  [C_0201]  136.89 94 180 bottom
CD300  1U_0201_6.3V6M  [C_0201]  143.33 110.55 90 bottom
CD301  10U_0402_6.3V6M  [C_0402]  140.75 99.08 0 top
CD302  1U_0201_6.3V6M  [C_0201]  119.81 97.02 270 top
CD303  1U_0201_6.3V6M  [C_0201]  143.46 109.96 180 top
CD304  1U_0201_6.3V6M  [C_0201]  130.31 95.38 270 bottom
CD305  1U_0201_6.3V6M  [C_0201]  119.8 96.61 270 bottom
CD306  1U_0201_6.3V6M  [C_0201]  119.8 98.46 270 bottom
CD307  1U_0201_6.3V6M  [C_0201]  130.27 102.43 90 bottom
CD308  1U_0201_6.3V6M  [C_0201]  137.82 94 0 bottom
CD309  1U_0201_6.3V6M  [C_0201]  131.94 94.06 180 bottom
CD310  10U_0402_6.3V6M  [C_0402]  132.71 93.94 180 top
CD311  1U_0201_6.3V6M  [C_0201]  119.8 108.65 90 bottom
CD312  1U_0201_6.3V6M  [C_0201]  143.43 110.56 180 top
CD313  1U_0201_6.3V6M  [C_0201]  119.77 100.65 90 bottom
CD314  1U_0201_6.3V6M  [C_0201]  112.82 93.94 180 top
CD315  1U_0201_6.3V6M  [C_0201]  132.86 94.06 0 bottom
CD316  0.047U_0201_10V6K  [C_0201]  119.72 104.82 270 bottom
CD317  1U_0201_6.3V6M  [C_0201]  130.27 97.91 90 bottom
CD318  10U_0402_6.3V6M  [C_0402]  144.97 110.31 90 bottom
CD319  1U_0201_6.3V6M  [C_0201]  130.29 108.63 90 bottom
CD320  0.047U_0402_10V7K  [C_0402]  104.39 105.82 90 top
CD321  0.047U_0402_10V7K  [C_0402]  114.84 105.44 270 top
CD322  0.047U_0201_10V6K  [C_0201]  93.95 105.29 90 bottom
CD323  0.047U_0201_10V6K  [C_0201]  104.38 106.03 270 bottom
CD324  0.022U_0402_16V7K~D  [C_0402]  134.59 78.43 90 bottom
CD325  1U_0201_6.3V6M  [C_0201]  104.4 97.87 270 bottom
CD326  10U_0402_6.3V6M  [C_0402]  129.32 93.94 0 top
CD327  1U_0201_6.3V6M  [C_0201]  105.65 110.38 180 bottom
CD328  1U_0402_6.3V6K  [C_0402]  89.96 109.24 180 top
CD329  10U_0402_6.3V6M  [C_0402]  118.84 93.99 180 top
CD330  330U_D3_2.5VY_R6M  [C_X]  96.19 79.97 180 top
CD331  1U_0402_6.3V6K  [C_0402]  93.94 108.03 270 top
CD332  1U_0402_6.3V6K  [C_0402]  104.39 97.54 270 top
CD333  1U_0402_6.3V6K  [C_0402]  93.93 109.43 180 top
CD334  1U_0201_6.3V6M  [C_0201]  114.84 98.46 270 bottom
CD335  1U_0201_6.3V6M  [C_0201]  114.77 101.1 90 bottom
CD336  1U_0201_6.3V6M  [C_0201]  89.96 109.24 180 bottom
CD337  1U_0201_6.3V6M  [C_0201]  90.03 104.54 180 bottom
CD338  1U_0402_6.3V6K  [C_0402]  93.89 101.16 90 top
CD339  10U_0402_6.3V6M  [C_0402]  109.99 93.94 0 top
CD340  10U_0402_6.3V6M  [C_0402]  108.07 93.94 180 top
CD341  1U_0402_6.3V6K  [C_0402]  90.03 104.54 180 top
CD342  10U_0402_6.3V6M  [C_0402]  91.09 104.6 270 bottom
CD343  1U_0201_6.3V6M  [C_0201]  93.95 98.93 270 bottom
CD344  1U_0402_6.3V6K  [C_0402]  104.38 109.35 90 top
CD345  1U_0201_6.3V6M  [C_0201]  104.37 107.22 270 bottom
CD346  1U_0201_6.3V6M  [C_0201]  102.38 110.38 0 bottom
CD347  10U_0402_6.3V6M  [C_0402]  116.05 108.96 90 bottom
CD348  10U_0402_6.3V6M  [C_0402]  91.03 104.43 270 top
CD349  1U_0402_6.3V6K  [C_0402]  90.03 105.43 180 top
CD350  1U_0402_6.3V6K  [C_0402]  94.41 94.06 180 top
CD351  10U_0402_6.3V6M  [C_0402]  91.03 108.35 90 top
CD352  1U_0402_6.3V6K  [C_0402]  104.39 94.87 90 top
CD353  10U_0402_6.3V6M  [C_0402]  100.59 93.94 0 top
CD354  10U_0402_6.3V6M  [C_0402]  105.29 93.94 0 top
CD355  1U_0201_6.3V6M  [C_0201]  104.38 101.81 90 bottom
CD356  1U_0201_6.3V6M  [C_0201]  104.37 95.83 90 bottom
CD357  10U_0402_6.3V6M  [C_0402]  95.83 93.94 0 top
CD358  10U_0402_6.3V6M  [C_0402]  98.61 93.94 180 top
CD359  1U_0402_6.3V6K  [C_0402]  104.38 108.49 270 top
CD360  1U_0201_6.3V6M  [C_0201]  93.95 109 270 bottom
CD361  1U_0201_6.3V6M  [C_0201]  90.03 105.43 180 bottom
CD362  1U_0201_6.3V6M  [C_0201]  93.89 101.16 90 bottom
CD363  10U_0402_6.3V6M  [C_0402]  91.03 108.35 90 bottom
CD364  1U_0201_6.3V6M  [C_0201]  89.96 108.35 180 bottom
CD365  10U_0402_6.3V6M  [C_0402]  103.86 93.94 180 top
CD366  10U_0402_6.3V6M  [C_0402]  115.92 108.07 90 top
CD367  1U_0201_6.3V6M  [C_0201]  114.84 95.85 270 bottom
CD368  1U_0402_6.3V6K  [C_0402]  114.84 100.04 270 top
CD369  10U_0402_6.3V6M  [C_0402]  137.54 93.94 180 top
CD370  1U_0201_6.3V6M  [C_0201]  114.91 108.97 90 bottom
CD371  1U_0402_6.3V6K  [C_0402]  93.87 96.91 270 top
CD372  1U_0402_6.3V6K  [C_0402]  114.86 101.03 90 top
CD373  1U_0402_6.3V6K  [C_0402]  89.96 108.35 180 top
CD374  1U_0402_6.3V6K  [C_0402]  93.94 105.34 90 top
CD375  1U_0402_6.3V6K  [C_0402]  114.84 108.08 90 top
CD376  1U_0402_6.3V6K  [C_0402]  104.37 101.73 90 top
CD377  1U_0201_6.3V6M  [C_0201]  114.91 107.22 270 bottom
CD378  100P_0201_50V8J  [C_0201]  137.78 110.37 0 top
CD379  100P_0201_50V8J  [C_0201]  140.83 98.35 0 top
CD380  100P_0201_50V8J  [C_0201]  140.78 107.57 270 top
CD381  100P_0201_50V8J  [C_0201]  119.8 109.28 90 top
CD382  100P_0201_50V8J  [C_0201]  119.2 107.21 270 top
CD383  100P_0201_50V8J  [C_0201]  140.97 108.39 90 top
CD384  100P_0201_50V8J  [C_0201]  140.6 100.22 270 bottom
CD385  100P_0201_50V8J  [C_0201]  130.29 96.93 270 bottom
CD386  100P_0201_50V8J  [C_0201]  136.53 110.32 180 bottom
CD387  100P_0201_50V8J  [C_0201]  119.8 107.99 270 bottom
CD388  100P_0201_50V8J  [C_0201]  118.75 110.14 270 bottom
CD389  100P_0201_50V8J  [C_0201]  143.43 109.39 180 top
CD390  100P_0201_50V8J  [C_0201]  113.7 110.37 0 top
CD391  100P_0201_50V8J  [C_0201]  116.67 108.07 270 top
CD392  100P_0201_50V8J  [C_0201]  89.91 106.58 180 top
CD393  100P_0201_50V8J  [C_0201]  93.87 104.56 270 top
CD394  100P_0201_50V8J  [C_0201]  93.93 110.2 180 top
CD395  100P_0201_50V8J  [C_0201]  89.9 107.49 180 top
CD396  100P_0201_50V8J  [C_0201]  113.7 110.37 0 bottom
CD397  100P_0201_50V8J  [C_0201]  128.08 110.43 0 bottom
CD398  100P_0201_50V8J  [C_0201]  89.94 106.75 180 bottom
CD399  100P_0201_50V8J  [C_0201]  93.93 109.8 90 bottom
CD400  100P_0201_50V8J  [C_0201]  95.87 110.41 180 bottom
CD401  100P_0201_50V8J  [C_0201]  89.94 107.49 180 bottom
CE1  0.01U_0402_16V7K  [C_0402]  135.44 27.26 180 top
CE2  0.01U_0402_16V7K  [C_0402]  135.44 30.18 180 top
CE5  0.1U_0402_25V6  [C_0402]  22.51 7.84 270 bottom
CE6  0.1U_0402_25V6  [C_0402]  19.1 13.16 180 bottom
CE7  10U_0603_6.3V6M  [C_0603]  25.63 19.3 0 top
CE8  0.1U_0402_25V6  [C_0402]  27.96 16.08 0 bottom
CE9  10U_0402_6.3V6M  [C_0402]  27.91 17.04 0 bottom
CE10  0.1U_0402_25V6  [C_0402]  28.09 10.62 0 bottom
CE11  10U_0402_6.3V6M  [C_0402]  28.1 9.48 0 bottom
CE12  27P_0402_50V8J  [C_0402]  18.18 8.72 0 bottom
CE42  0.1U_0201_10V6K  [C_0201]  37.94 18.47 180 top
CE43  0.1U_0201_10V6K  [C_0201]  47.56 8.85 0 bottom
CE44  1U_0402_6.3V6K  [C_0402]  44.24 15.58 180 bottom
CE45  0.1U_0201_10V6K  [C_0201]  45.14 15.45 0 bottom
CE46  10U_0402_6.3V6M  [C_0402]  43.02 6.88 90 bottom
CE47  22U_0402_6.3V6M  [C_0402]  41.88 13.73 270 bottom
CE48  0.1U_0201_10V6K  [C_0201]  40.87 13.33 270 bottom
CE49  0.1U_0201_10V6K  [C_0201]  40.66 10.54 0 bottom
CE50  0.1U_0201_10V6K  [C_0201]  46.39 12.4 0 bottom
CE51  0.1U_0201_10V6K  [C_0201]  40.38 11.81 0 bottom
CE52  12P_0402_50V8J  [C_0402]  43.3 5.86 180 bottom
CE53  68P_0402_50V8J  [C_0402]  43.3 4.97 180 bottom
CE54  0.1U_0201_10V6K  [C_0201]  33.92 10.7 180 bottom
CE55  0.1U_0201_10V6K  [C_0201]  44 6.69 0 bottom
CE56  0.1U_0201_10V6K  [C_0201]  53.08 7.96 0 top
CE57  10P_0402_50V8J  [C_0402]  38.15 13.7 180 top
CE58  2200P_0402_50V7K  [C_0402]  47.61 19.7 180 top
CE59  2200P_0402_50V7K  [C_0402]  50.02 19.7 180 top
CE60  2200P_0402_50V7K  [C_0402]  37.64 8.34 180 top
CE61  2200P_0402_50V7K  [C_0402]  35.99 11.64 180 top
CE62  2200P_0402_50V7K  [C_0402]  52.12 19.64 180 top
CE63  1U_0402_6.3V6K  [C_0402]  53.57 11.82 90 top
CE64  1U_0402_6.3V6K  [C_0402]  38.02 11.85 180 top
CE65  33P_0402_50V8J  [C_0402]  26.65 22.75 180 bottom
CE66  12P_0402_50V8J  [C_0402]  40.43 20.28 180 top
CE67  12P_0402_50V8J  [C_0402]  41.36 20.28 0 top
CE70  0.1U_0201_10V6K  [C_0201]  9.74 69.11 180 bottom
CE71  10P_0402_25V8J  [C_0402]  11.45 64.34 0 bottom
CE75  4700P_0402_25V7K  [C_0402]  52.93 9.86 0 top
CE78  4700P_0402_25V7K  [C_0402]  35.14 14.13 180 top
CE79  0.1U_0402_25V6  [C_0402]  52.92 18.56 0 top
CE83  100P_0201_50V8J  [C_0201]  106.23 77.55 0 top
CE86  0.1U_0402_25V6  [C_0402]  38.02 10.28 180 top
CE87  100P_0201_50V8J  [C_0201]  117.14 104.1 180 bottom
CE90  2200P_0402_50V7K  [C_0402]  48.88 20.85 180 top
CE93  100P_0201_50V8J  [C_0201]  155.61 13.37 90 top
CE94  100P_0201_50V8J  [C_0201]  42.87 71.46 0 top
CE95  100P_0201_50V8J  [C_0201]  77.17 18.81 0 bottom
CE101  2.2U_0402_6.3V6M  [C_0402]  36.04 18.55 90 top
CE103  1U_0402_6.3V6K  [C_0402]  35.15 18.55 90 top
CE104  100P_0201_50V8J  [C_0201]  38.07 22.79 270 top
CE105  100P_0201_50V8J  [C_0201]  96.87 44.66 270 top
CH36  0.1U_0402_10V7K  [C_0402]  80.31 108.29 180 bottom
CH37  10U_0603_6.3V6M  [C_0603]  111.29 63.46 90 top
CH38  10U_0603_6.3V6M  [C_0603]  112.43 77.49 180 top
CH39  10U_0603_6.3V6M  [C_0603]  111.29 62.44 270 top
CH40  1U_0402_6.3V6K  [C_0402]  108.73 60.97 0 top
CH41  1U_0402_6.3V6K  [C_0402]  108.73 61.85 0 top
CH42  1U_0402_6.3V6K  [C_0402]  108.73 62.74 0 top
CH43  1U_0402_6.3V6K  [C_0402]  108.73 63.63 0 top
CH44  0.1U_0201_10V6K  [C_0201]  51.37 42.17 0 bottom
CH45  0.1U_0201_10V6K  [C_0201]  51.37 41.55 0 bottom
CH46  22U_0603_6.3V6M  [C_0603]  110.52 48.22 180 top
CH47  22U_0603_6.3V6M  [C_0603]  110.52 49.49 180 top
CH48  22U_0603_6.3V6M  [C_0603]  110.52 50.76 180 top
CH49  22U_0603_6.3V6M  [C_0603]  112.37 51.45 270 bottom
CH50  22U_0603_6.3V6M  [C_0603]  113.64 51.45 270 bottom
CH51  22U_0603_6.3V6M  [C_0603]  110.14 45.68 180 top
CH52  22U_0603_6.3V6M  [C_0603]  110.52 46.95 180 top
CH53  1U_0402_6.3V6K  [C_0402]  112.57 79.14 180 top
CH54  1U_0402_6.3V6K  [C_0402]  112.57 80.16 180 top
CH57  22U_0603_6.3V6M  [C_0603]  114.84 68.28 0 top
CH58  220U_D7_2VM_R6M  [C_EEFSS0D221R]  119.5 71.46 180 top
CH59  47U_0603_6.3V6M  [C_0603]  114.84 61.3 0 top
CH60  47U_0603_6.3V6M  [C_0603]  113.83 61.3 180 top
CH62  22U_0603_6.3V6M  [C_0603]  102.14 79.2 180 top
CH63  22U_0603_6.3V6M  [C_0603]  103.16 79.2 0 top
CH64  22U_0603_6.3V6M  [C_0603]  109.89 81.74 180 top
CH65  22U_0603_6.3V6M  [C_0603]  118.34 80.28 90 top
CH66  10U_0603_6.3V6M  [C_0603]  98.33 80.47 0 top
CH67  10U_0603_6.3V6M  [C_0603]  102.14 80.47 180 top
CH68  10U_0603_6.3V6M  [C_0603]  103.16 80.47 0 top
CH69  10U_0603_6.3V6M  [C_0603]  103.16 81.74 0 top
CH70  10U_0603_6.3V6M  [C_0603]  102.14 81.74 180 top
CH71  10U_0603_6.3V6M  [C_0603]  115.29 80.28 90 top
CH72  10U_0603_6.3V6M  [C_0603]  113.76 80.28 90 top
CH75  8.2P_0402_50V8D  [C_0402]  22.27 37.81 270 bottom
CH76  8.2P_0402_50V8D  [C_0402]  22.27 40.35 90 bottom
CH77  15P_0402_50V8J  [C_0402]  48.68 30.98 90 bottom
CH78  15P_0402_50V8J  [C_0402]  46.01 30.98 90 bottom
CH79  1U_0402_6.3V6K  [C_0402]  17.83 41.93 180 bottom
CH80  1U_0402_6.3V6K  [C_0402]  17.83 37.93 180 bottom
CH81  10P_0402_25V8J  [C_0402]  27.67 40.18 270 top
CH82  10P_0402_25V8J  [C_0402]  29.31 38.51 270 top
CH84  15P_0402_50V8J  [C_0402]  18.08 43.71 180 top
CH86  1U_0402_6.3V6K  [C_0402]  27.87 49.31 0 top
CH88  0.1U_0402_10V7K  [C_0402]  27.83 48.22 0 top
CH89  1U_0402_6.3V6K  [C_0402]  37.11 41.23 0 top
CH90  22U_0603_6.3V6M  [C_0603]  41.82 35.96 90 top
CH91  22U_0603_6.3V6M  [C_0603]  40.61 35.96 90 top
CH92  1U_0402_6.3V6K  [C_0402]  42.9 36.2 90 top
CH93  22U_0603_6.3V6M  [C_0603]  51.03 57.55 270 bottom
CH94  22U_0603_6.3V6M  [C_0603]  51.03 58.57 90 bottom
CH95  1U_0402_6.3V6K  [C_0402]  48.05 60.41 180 bottom
CH96  22U_0603_6.3V6M  [C_0603]  39.81 45.46 0 top
CH97  1U_0402_6.3V6K  [C_0402]  39.81 46.61 0 top
CH98  22U_0603_6.3V6M  [C_0603]  33.12 37.1 270 top
CH99  22U_0603_6.3V6M  [C_0603]  33.12 38.5 90 top
CH100  0.1U_0402_10V7K  [C_0402]  35.28 55.66 270 top
CH101  1U_0402_6.3V6K  [C_0402]  38.48 42.55 180 top
CH102  0.1U_0402_10V7K  [C_0402]  30.63 38.44 0 top
CH103  0.1U_0402_10V7K  [C_0402]  26.55 55.7 0 top
CH104  0.1U_0402_10V7K  [C_0402]  32.74 55.28 270 top
CH105  1U_0402_6.3V6K  [C_0402]  27.83 45.68 0 top
CH106  0.1U_0402_10V7K  [C_0402]  27.83 46.56 0 top
CH107  1U_0402_6.3V6K  [C_0402]  27.91 43.97 270 top
CH108  0.1U_0402_10V7K  [C_0402]  28.8 43.97 270 top
CH114  0.1U_0201_6.3V6K  [C_0201]  107.06 23.13 0 bottom
CH115  0.1U_0201_6.3V6K  [C_0201]  107.06 22.5 0 bottom
CH116  22P_0402_50V8J  [C_0402]  83.79 14.74 90 bottom
CH117  2.2P_0201_25V8C  [C_0201]  28.55 40.38 270 top
CH118  2.2P_0201_25V8C  [C_0201]  27.87 42.12 0 top
CH119  2.2P_0201_25V8C  [C_0201]  23.76 38.63 180 bottom
CH120  2.2P_0201_25V8C  [C_0201]  22.42 36.21 180 bottom
CH121  2.2P_0201_25V8C  [C_0201]  28.55 37.76 90 top
CH122  2.2P_0201_25V8C  [C_0201]  32.14 42.25 180 top
CH123  2.2P_0201_25V8C  [C_0201]  31.58 44.59 0 top
CH124  0.1U_0201_10V6K  [C_0201]  71.6 9.75 270 bottom
CH125  1U_0402_6.3V6K  [C_0402]  84.38 60.92 180 top
CH126  1U_0201_6.3V6M  [C_0201]  84.43 68.26 270 top
CH127  22U_0603_6.3V6M  [C_0603]  108.8 73.85 180 top
CH128  22U_0603_6.3V6M  [C_0603]  109.5 65.93 0 top
CH130  22U_0603_6.3V6M  [C_0603]  109.5 67.15 0 top
CH131  1U_0201_6.3V6M  [C_0201]  105.29 54.63 180 bottom
CH132  1U_0201_6.3V6M  [C_0201]  105.29 54.06 180 bottom
CH133  1U_0201_6.3V6M  [C_0201]  105.98 54.63 0 bottom
CH134  1U_0201_6.3V6M  [C_0201]  105.98 54.06 0 bottom
CH135  22U_0603_6.3V6M  [C_0603]  107.81 51.15 180 bottom
CH136  22U_0603_6.3V6M  [C_0603]  107.81 52.37 180 bottom
CH137  1U_0201_6.3V6M  [C_0201]  107.25 54.06 0 bottom
CH138  1U_0201_6.3V6M  [C_0201]  107.25 54.63 0 bottom
CH139  22U_0603_6.3V6M  [C_0603]  81.9 66 0 top
CH140  22U_0603_6.3V6M  [C_0603]  81.9 64.76 0 top
CH141  1U_0402_6.3V6K  [C_0402]  79.49 66.19 90 top
CH142  1U_0402_6.3V6K  [C_0402]  79.5 65.35 270 top
CH181  1U_0402_6.3V6K  [C_0402]  106.97 61.83 0 top
CH182  1U_0402_6.3V6K  [C_0402]  105.83 62.71 90 top
CH183  1U_0402_6.3V6K  [C_0402]  106.14 60.94 180 top
CH184  1U_0402_6.3V6K  [C_0402]  106.14 61.83 180 top
CH185  1U_0402_6.3V6K  [C_0402]  106.98 60.94 0 top
CH186  10U_0402_6.3V6M  [C_0402]  107.64 62.71 90 top
CH187  10U_0402_6.3V6M  [C_0402]  106.74 62.71 90 top
CH188  1U_0201_6.3V6M  [C_0201]  87.8 60.79 0 top
CH189  1U_0201_6.3V6M  [C_0201]  87.8 61.96 0 top
CH190  1U_0201_6.3V6M  [C_0201]  85.86 62.06 180 top
CH191  1U_0201_6.3V6M  [C_0201]  85.86 61.42 180 top
CH192  1U_0201_6.3V6M  [C_0201]  87.8 61.37 0 top
CH193  1U_0201_6.3V6M  [C_0201]  85.86 60.79 180 top
CH194  47U_0603_6.3V6M  [C_0603]  87.79 62.72 90 top
CH195  47U_0603_6.3V6M  [C_0603]  86.23 63.06 180 top
CH198  47U_0603_6.3V6M  [C_0603]  87.66 65.19 0 top
CH199  47U_0603_6.3V6M  [C_0603]  86.65 66.38 180 top
CH200  47U_0603_6.3V6M  [C_0603]  86.65 67.65 180 top
CH201  47U_0603_6.3V6M  [C_0603]  87.66 66.43 0 top
CH202  47U_0603_6.3V6M  [C_0603]  87.66 67.67 0 top
CH203  47U_0603_6.3V6M  [C_0603]  86.65 65.11 180 top
CH204  1U_0201_6.3V6M  [C_0201]  103.32 52.85 0 bottom
CH205  1U_0201_6.3V6M  [C_0201]  104.49 62.58 0 top
CH206  1U_0201_6.3V6M  [C_0201]  103.32 54.06 0 bottom
CH207  1U_0201_6.3V6M  [C_0201]  103.87 62.58 180 top
CH208  1U_0201_6.3V6M  [C_0201]  104.49 63.72 0 top
CH209  1U_0201_6.3V6M  [C_0201]  103.32 53.49 0 bottom
CH210  1U_0201_6.3V6M  [C_0201]  104.49 63.15 0 top
CH211  1U_0201_6.3V6M  [C_0201]  103.32 54.63 0 bottom
CH212  1U_0201_6.3V6M  [C_0201]  103.87 63.72 180 top
CH213  1U_0201_6.3V6M  [C_0201]  103.87 63.15 180 top
CH214  47U_0603_6.3V6M  [C_0603]  105.67 64.65 0 top
CH215  47U_0603_6.3V6M  [C_0603]  104.72 64.61 180 top
CH220  100U_1206_6.3V6M  [C_1206]  107.16 69.23 90 top
CH221  100U_1206_6.3V6M  [C_1206]  105 69.23 90 top
CH223  0.1U_0201_10V6K  [C_0201]  79.28 61.45 90 top
CH224  0.1U_0201_10V6K  [C_0201]  80.17 61.4 270 top
CH228  10U_0603_6.3V6M  [C_0603]  116.81 80.28 90 top
CH229  10U_0603_6.3V6M  [C_0603]  98.33 79.2 0 top
CH230  10U_0603_6.3V6M  [C_0603]  110.91 81.74 0 top
CH231  10U_0603_6.3V6M  [C_0603]  98.33 81.74 0 top
CH232  1U_0402_6.3V6K  [C_0402]  110.08 78.26 270 top
CH233  1U_0402_6.3V6K  [C_0402]  109.19 78.26 270 top
CH234  0.1U_0402_10V7K  [C_0402]  81.38 51.02 270 bottom
CH236  0.1U_0201_10V6K  [C_0201]  104.33 89.24 0 bottom
CH237  0.01U_0402_16V7K  [C_0402]  59.66 19.59 270 top
CH238  1U_0201_6.3V6M  [C_0201]  58.23 24.34 0 top
CH239  0.1U_0402_10V7K  [C_0402]  63.86 23.58 180 top
CH240  15P_0201_25V8J  [C_0201]  83.92 53.64 90 bottom
CH241  1U_0402_6.3V6K  [C_0402]  163.65 9.94 0 bottom
CH242  1U_0201_6.3V6M  [C_0201]  61.69 15.92 90 top
CH243  0.1U_0402_10V7K  [C_0402]  33.83 60.09 180 bottom
CLRC  SHORT PADS  [SHORTPADS]  17.37 36.79 180 bottom
CLRME  SHORT PADS  [SHORTPADS]  17.37 39.96 180 bottom
CP1  0.1U_0402_10V7K  [C_0402]  41.82 72.78 90 top
CP2  1U_0603_10V7K  [C_0603]  40.61 72.28 90 top
CP3  0.1U_0402_10V7K  [C_0402]  36.53 66.37 90 top
CP4  0.1U_0402_10V7K  [C_0402]  35.37 66.23 180 top
CP5  1U_0402_6.3V6K  [C_0402]  35.37 67.16 180 top
CP6  1U_0402_6.3V6K  [C_0402]  34.46 65.34 0 top
CP7  0.1U_0402_10V7K  [C_0402]  31.72 66.3 90 top
CP8  1U_0402_6.3V6K  [C_0402]  32.74 66.3 90 top
CP9  390P_0402_50V7K  [C_0402]  34.37 70.8 270 top
CP10  390P_0402_50V7K  [C_0402]  31.18 70.03 0 top
CP11  390P_0402_50V7K  [C_0402]  35.28 71.02 270 top
CP12  390P_0402_50V7K  [C_0402]  31.18 69.09 0 top
CP13  0.1U_0402_10V7K  [C_0402]  34.09 69 180 top
CP14  1000P_0201_50V7K  [C_0201]  19.71 69.07 0 bottom
CP15  0.1U_0201_10V6K  [C_0201]  24.04 69.07 0 bottom
CP16  1000P_0201_50V7K  [C_0201]  22.21 100.32 90 top
CP17  0.1U_0201_10V6K  [C_0201]  28.22 102.23 270 top
CP18  0.1U_0201_10V6K  [C_0201]  23.24 69.07 180 bottom
CP19  0.1U_0201_10V6K  [C_0201]  21.61 102.08 0 top
CP20  10U_0402_10V6M  [C_0402]  22.7 64.74 270 bottom
CP21  10U_0402_10V6M  [C_0402]  26.07 66.9 270 bottom
CP22  47U_0603_6.3V  [C_0603]  22.32 75.14 180 bottom
CP23  47U_0603_6.3V  [C_0603]  28.99 101.92 0 top
CP24  10U_0402_10V6M  [C_0402]  29.49 97.24 0 bottom
CP25  10U_0402_10V6M  [C_0402]  29.75 94.96 270 bottom
CR1  0.1U_0402_10V7K  [C_0402]  20.75 61.28 180 top
CR2  10U_0402_6.3V6M  [C_0402]  22.95 69.61 0 top
CR3  4.7U_0402_6.3V6M  [C_0402]  20.75 60.33 180 top
CR4  0.1U_0402_10V7K  [C_0402]  22.82 68.73 0 top
CR5  1U_0402_6.3V6K  [C_0402]  18.21 66 180 top
CR6  0.1U_0402_10V7K  [C_0402]  52.28 46.31 0 bottom
CR7  0.1U_0402_10V7K  [C_0402]  52.28 45.42 0 bottom
CR8  0.1U_0402_10V7K  [C_0402]  26.97 65.68 180 top
CR9  0.1U_0402_10V7K  [C_0402]  26.97 66.57 180 top
CR10  10P_0402_25V8J  [C_0402]  17.29 66.88 0 top
CR11  10U_0402_6.3V6M  [C_0402]  17.29 64.22 0 top
CR12  0.1U_0402_10V7K  [C_0402]  17.29 65.11 0 top
CR13  1U_0402_6.3V6K  [C_0402]  18.21 60.92 180 top
CR14  4.7U_0402_6.3V6M  [C_0402]  5.03 66.12 180 bottom
CR15  0.1U_0402_10V7K  [C_0402]  5.03 65.11 180 bottom
CR16  4.7U_0402_6.3V6M  [C_0402]  22.07 69.67 90 top
CR17  0.1U_0402_10V7K  [C_0402]  21.89 68.66 180 top
CR18  0.1U_0402_10V7K  [C_0402]  24.6 68.73 0 top
CT2  0.22U_0201_6.3V6M  [C_0201]  41.19 73.9 90 bottom
CT4  0.22U_0201_6.3V6M  [C_0201]  40.63 73.9 90 bottom
CT5  0.22U_0201_6.3V6M  [C_0201]  54.92 52.11 180 bottom
CT6  0.22U_0201_6.3V6M  [C_0201]  37.5 73.9 90 bottom
CT7  0.22U_0201_6.3V6M  [C_0201]  53.37 53.78 180 bottom
CT8  0.22U_0201_6.3V6M  [C_0201]  36.94 73.9 90 bottom
CT9  0.22U_0201_6.3V6M  [C_0201]  53.39 54.72 180 bottom
CT10  0.22U_0201_6.3V6M  [C_0201]  36.32 73.9 90 bottom
CT11  0.22U_0201_6.3V6M  [C_0201]  53.39 55.28 180 bottom
CT12  0.22U_0201_6.3V6M  [C_0201]  35.76 73.9 90 bottom
CT13  0.1U_0201_6.3V6K  [C_0201]  46.29 83.33 0 bottom
CT14  0.1U_0201_6.3V6K  [C_0201]  46.29 82.76 0 bottom
CT15  0.1U_0201_6.3V6K  [C_0201]  44.66 82.16 0 bottom
CT16  0.1U_0201_6.3V6K  [C_0201]  46.31 81.26 0 bottom
CT17  0.1U_0201_6.3V6K  [C_0201]  44.66 80.38 0 bottom
CT18  0.1U_0201_6.3V6K  [C_0201]  44.66 80.94 0 bottom
CT19  0.22U_0201_6.3V6M  [C_0201]  38.59 73.9 90 bottom
CT20  0.22U_0201_6.3V6M  [C_0201]  54.92 52.67 180 bottom
CT21  0.22U_0201_6.3V6M  [C_0201]  39.15 73.9 90 bottom
CT22  0.22U_0201_6.3V6M  [C_0201]  53.37 53.22 180 bottom
CT23  0.1U_0201_6.3V6K  [C_0201]  44.65 82.73 0 bottom
CT24  0.1U_0201_6.3V6K  [C_0201]  46.31 81.82 0 bottom
CT25  0.1U_0201_6.3V6K  [C_0201]  47.67 84.69 0 bottom
CT26  0.1U_0201_6.3V6K  [C_0201]  47.67 85.25 0 bottom
CT27  0.1U_0201_6.3V6K  [C_0201]  46.31 79.49 0 bottom
CT28  0.1U_0201_6.3V6K  [C_0201]  46.31 80.05 0 bottom
CT29  0.1U_0201_6.3V6K  [C_0201]  44.66 79.17 0 bottom
CT30  0.1U_0201_6.3V6K  [C_0201]  44.66 78.61 0 bottom
CT31  0.1U_0201_6.3V6K  [C_0201]  46.31 77.72 0 bottom
CT32  0.1U_0201_6.3V6K  [C_0201]  46.31 78.28 0 bottom
CT33  0.1U_0201_6.3V6K  [C_0201]  44.66 77.4 0 bottom
CT34  0.1U_0201_6.3V6K  [C_0201]  44.66 76.84 0 bottom
CT35  0.1U_0201_6.3V6K  [C_0201]  47.67 83.51 0 bottom
CT36  0.1U_0201_6.3V6K  [C_0201]  47.67 84.07 0 bottom
CT37  27P_0201_25V8  [C_0201]  30.54 74.42 270 bottom
CT38  27P_0201_25V8  [C_0201]  30.54 76.18 90 bottom
CT39  0.22U_0201_6.3V6M  [C_0201]  31.12 79.52 180 bottom
CT40  0.22U_0201_6.3V6M  [C_0201]  31.12 83.08 180 bottom
CT41  0.22U_0201_6.3V6M  [C_0201]  31.12 78.94 180 bottom
CT42  0.22U_0201_6.3V6M  [C_0201]  31.12 82.44 180 bottom
CT43  0.22U_0201_6.3V6M  [C_0201]  31.12 77.74 180 bottom
CT44  0.22U_0201_6.3V6M  [C_0201]  31.12 81.17 180 bottom
CT45  0.22U_0201_6.3V6M  [C_0201]  31.12 78.33 180 bottom
CT46  0.22U_0201_6.3V6M  [C_0201]  31.12 81.81 180 bottom
CT47  0.1U_0201_6.3V6K  [C_0201]  43.02 75.24 270 top
CT48  0.1U_0201_6.3V6K  [C_0201]  41.88 75.24 270 top
CT49  0.1U_0201_6.3V6K  [C_0201]  42.45 75.24 270 top
CT50  0.1U_0201_6.3V6K  [C_0201]  41.31 75.24 270 top
CT51  0.1U_0201_6.3V6K  [C_0201]  52.8 101.85 270 bottom
CT52  1U_0201_6.3V6M  [C_0201]  41.07 81.87 90 top
CT53  1U_0201_6.3V6M  [C_0201]  37.86 83.17 180 top
CT54  1U_0201_6.3V6M  [C_0201]  41.07 81.18 270 top
CT55  1U_0201_6.3V6M  [C_0201]  37.19 81.22 180 top
CT56  1U_0201_6.3V6M  [C_0201]  40.46 81.87 90 top
CT57  1U_0201_6.3V6M  [C_0201]  39.8 81.87 90 top
CT58  1U_0201_6.3V6M  [C_0201]  37.86 83.81 0 top
CT59  0.1U_0201_10V6K  [C_0201]  39.16 83.83 90 top
CT60  1U_0201_6.3V6M  [C_0201]  34.71 83.13 180 top
CT61  1U_0201_6.3V6M  [C_0201]  32.67 86.95 90 top
CT62  10U_0402_6.3V6M  [C_0402]  30.96 86.05 90 bottom
CT63  10U_0402_6.3V6M  [C_0402]  31.02 87.53 90 top
CT64  10U_0402_6.3V6M  [C_0402]  31.91 87.53 90 top
CT65  10U_0402_6.3V6M  [C_0402]  30.07 86.05 90 bottom
CT66  1U_0201_6.3V6M  [C_0201]  39.15 79.91 0 top
CT67  1U_0201_6.3V6M  [C_0201]  37.86 79.27 0 top
CT68  1U_0201_6.3V6M  [C_0201]  37.21 77.97 270 top
CT69  1U_0201_6.3V6M  [C_0201]  37.86 80.56 90 top
CT70  1U_0201_6.3V6M  [C_0201]  37.86 79.91 0 top
CT71  1U_0201_6.3V6M  [C_0201]  39.72 79.27 270 top
CT72  1U_0201_6.3V6M  [C_0201]  35.25 80.56 270 top
CT73  1U_0201_6.3V6M  [C_0201]  35.26 81.22 0 top
CT74  1U_0201_6.3V6M  [C_0201]  34.6 80.56 180 top
CT75  1U_0201_6.3V6M  [C_0201]  37.21 82.51 270 top
CT76  1U_0201_6.3V6M  [C_0201]  34.6 81.86 180 top
CT77  1U_0201_6.3V6M  [C_0201]  36.62 83.14 90 top
CT78  1U_0201_6.3V6M  [C_0201]  37.84 82.51 270 top
CT79  47U_0603_6.3V  [C_0603]  29.01 88.81 180 bottom
CT80  47U_0603_6.3V  [C_0603]  29.01 90 180 bottom
CT81  47U_0603_6.3V  [C_0603]  29.01 91.19 180 bottom
CT82  1U_0201_6.3V6M  [C_0201]  39.15 82.52 180 top
CT83  1U_0201_6.3V6M  [C_0201]  39.81 83.15 0 top
CT84  1U_0201_6.3V6M  [C_0201]  39.15 81.86 180 top
CT85  10U_0402_6.3V6M  [C_0402]  34.52 78.61 270 top
CT86  10U_0402_6.3V6M  [C_0402]  33.63 78.61 270 top
CT87  1U_0201_6.3V6M  [C_0201]  34.62 79.33 90 top
CT88  1U_0201_6.3V6M  [C_0201]  36.56 81.87 90 top
CT89  1U_0201_6.3V6M  [C_0201]  37.21 79.94 90 top
CT90  1U_0201_6.3V6M  [C_0201]  36.6 79.94 90 top
CT91  1U_0201_6.3V6M  [C_0201]  39.18 80.56 180 top
CT92  47U_0603_6.3V  [C_0603]  28.61 85.17 90 top
CT93  47U_0603_6.3V  [C_0603]  29.94 84.09 180 top
CT94  0.22U_0201_6.3V6M  [C_0201]  53.37 51.8 180 bottom
CT95  0.22U_0201_6.3V6M  [C_0201]  53.37 51.24 180 bottom
CT97  0.47U_0402_25V6K  [C_0402]  14.63 75.66 270 bottom
CT98  0.47U_0402_25V6K  [C_0402]  15.5 76.21 0 bottom
CT101  0.47U_0402_25V6K  [C_0402]  11.45 74.86 0 top
CT102  0.47U_0402_25V6K  [C_0402]  13.71 74.75 90 bottom
CT107  0.47U_0402_25V6K  [C_0402]  11.27 104.95 0 bottom
CT108  0.47U_0402_25V6K  [C_0402]  12.19 105.86 180 bottom
CT111  0.47U_0402_25V6K  [C_0402]  14.14 104.84 180 bottom
CT112  0.47U_0402_25V6K  [C_0402]  13.23 105.73 0 bottom
CT129  0.1U_0402_25V6  [C_0402]  47.33 89.87 0 bottom
CT130  0.1U_0402_25V6  [C_0402]  47.7 87.15 270 top
CV229  8.2P_0402_50V8D  [C_0402]  57.44 94.52 270 top
CV230  10U_0603_6.3V6M  [C_0603]  56.36 94.51 270 top
CV231  1U_0603_25V6  [C_0603]  61.2 98.6 0 top
CV232  0.1U_0402_25V6  [C_0402]  65.78 95.69 90 top
CV233  0.1U_0402_10V7K  [C_0402]  49.95 95.54 270 top
CV234  0.1U_0402_10V7K  [C_0402]  49.06 95.54 270 top
CV235  0.1U_0201_10V6K  [C_0201]  146.68 101.24 0 top
CV237  0.1U_0402_10V7K  [C_0402]  48.17 95.54 270 top
CV238  0.1U_0402_10V7K  [C_0402]  47.28 95.54 270 top
CV239  0.1U_0402_10V7K  [C_0402]  46.39 95.54 270 top
CV240  0.1U_0402_10V7K  [C_0402]  45.5 95.54 270 top
CV241  0.1U_0402_10V7K  [C_0402]  44.6 95.1 270 top
CV242  0.1U_0402_10V7K  [C_0402]  43.71 95.1 270 top
CV243  0.1U_0402_10V7K  [C_0402]  51.72 95.54 270 top
CV244  0.1U_0402_10V7K  [C_0402]  50.83 95.54 270 top
CV245  1U_0402_25V6K  [C_0402]  118.16 18.99 90 top
CV246  0.1U_0201_25V6K  [C_0201]  116.05 16.13 0 top
CV247  8.2P_0402_50V8D  [C_0402]  146.26 97.94 0 top
CV248  0.1U_0402_10V7K  [C_0402]  52.67 94.8 90 top
CZ3  2200P_0402_25V7K  [C_0402]  91.87 27.01 180 bottom
CZ4  2200P_0402_25V7K  [C_0402]  27.2 27.77 0 top
CZ5  1U_0402_6.3V6K  [C_0402]  97.3 28.15 0 bottom
CZ6  1U_0402_6.3V6K  [C_0402]  23.52 30.31 0 top
CZ7  10U_0603_6.3V6M  [C_0603]  89.38 28.28 270 bottom
CZ8  10U_0603_6.3V6M  [C_0603]  28.86 30.82 180 top
CZ9  1U_0402_6.3V6K  [C_0402]  22.64 29.79 90 bottom
CZ10  0.1U_0402_10V7K  [C_0402]  22.64 32.54 270 bottom
CZ11  2200P_0402_25V7K  [C_0402]  20.37 33.55 180 bottom
CZ12  1U_0402_6.3V6K  [C_0402]  54.71 104.3 270 bottom
CZ13  0.1U_0402_10V7K  [C_0402]  55.73 100.31 0 bottom
CZ14  2200P_0402_25V7K  [C_0402]  58.23 101.32 90 bottom
CZ17  470P_0402_50V8J  [C_0402]  82.01 24.59 180 bottom
CZ18  0.1U_0402_10V7K  [C_0402]  85.19 23.88 90 bottom
CZ19  0.1U_0402_10V7K  [C_0402]  63.29 92.28 180 bottom
CZ20  0.1U_0402_10V7K  [C_0402]  112.73 28.17 0 top
CZ21  1U_0402_6.3V6K  [C_0402]  110.43 25.54 270 top
CZ27  0.1U_0402_10V7K  [C_0402]  83.66 27.18 90 bottom
CZ28  1U_0402_6.3V6K  [C_0402]  78.33 26.32 270 bottom
CZ29  0.1U_0402_10V7K  [C_0402]  78.33 27.31 90 bottom
CZ30  0.1U_0402_10V7K  [C_0402]  85.95 28.1 270 bottom
CZ31  2200P_0402_25V7K  [C_0402]  116.11 96.78 90 top
CZ32  0.1U_0402_10V7K  [C_0402]  116.11 94.94 90 top
CZ33  1U_0201_6.3V6M  [C_0201]  146.68 100.67 0 top
CZ34  0.1U_0402_10V7K  [C_0402]  150.49 98.14 180 top
D18  AZ5B25-01F_DFN0603P2Y2  [ESD101-B1-02ELS_TSSLP-2-4-2]  55.47 95.9 0 top
D72  AZ5B25-01F_DFN0603P2Y2  [ESD101-B1-02ELS_TSSLP-2-4-2]  146.05 105.77 90 top
D74  AZ5B25-01F_DFN0603P2Y2  [ESD101-B1-02ELS_TSSLP-2-4-2]  52.61 94.04 0 top
D321  RB751S40T1G_SOD523-2  [AZ5125-01HPR7G_SOD523-2]  67.31 24.58 90 top
D429  -  [TVNST52302AB0_SOT523-3]  55.29 42.35 90 bottom
DE1  RB751S40T1G_SOD523-2  [AZ5125-01HPR7G_SOD523-2]  137.86 27.26 180 top
DE2  RB751S40T1G_SOD523-2  [AZ5125-01HPR7G_SOD523-2]  37.15 26.86 270 top
DE3  RB751S40T1G_SOD523-2  [AZ5125-01HPR7G_SOD523-2]  137.86 30.18 180 top
DH1  RB751S40T1G_SOD523-2  [AZ5125-01HPR7G_SOD523-2]  16.61 46.56 0 bottom
DI5  -  [TVNST52302AB0_SOT523-3]  156.7 8.92 90 bottom
DL1  AZ5125-02S.R7G_SOT23-3  [AZ5125-02SPR7G_SOT23-3]  9.65 53.3 90 top
DT1  AZ4520-01F.R7G_DFN1610P2E2  [AZ4520-01FPR7G_DFN1610P2E2]  12.51 75.53 180 bottom
DT3  ESD8011MUT5G X3DFN2  [ESD108-B1-CSP0201_WLL-2-1-2]  11.31 78.76 270 bottom
DT4  ESD8011MUT5G X3DFN2  [ESD108-B1-CSP0201_WLL-2-1-2]  11.31 78.76 270 top
DT7  ESD8011MUT5G X3DFN2  [ESD108-B1-CSP0201_WLL-2-1-2]  11.31 79.52 90 bottom
DT8  ESD8011MUT5G X3DFN2  [ESD108-B1-CSP0201_WLL-2-1-2]  11.31 79.52 90 top
DT11  ESD8011MUT5G X3DFN2  [ESD108-B1-CSP0201_WLL-2-1-2]  11.31 80.98 270 bottom
DT12  ESD8011MUT5G X3DFN2  [ESD108-B1-CSP0201_WLL-2-1-2]  11.31 80.98 270 top
DT15  ESD8011MUT5G X3DFN2  [ESD108-B1-CSP0201_WLL-2-1-2]  11.31 82.12 270 bottom
DT16  ESD8011MUT5G X3DFN2  [ESD108-B1-CSP0201_WLL-2-1-2]  11.31 82.12 270 top
